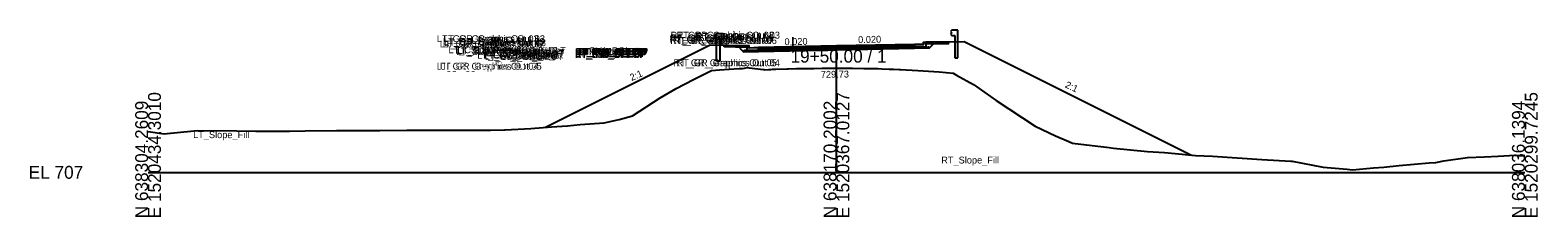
# Model space of a CAD drawing. Extents: x -26 to 3903, y -10 to 9531.
# Drawn here: x -25.7 to 302.8, y 9490.3 to 9531 of the extents above; entities that cross this region are included whole.
import ezdxf

# ---------------------------------------------------------------- set-up
doc = ezdxf.new("R2010")
doc.units = 0
for name, color, linetype in [('Default', 7, 'Continuous'), ('Exist Cross Section Cell', 7, 'Continuous'), ('Exist XS Center Line Elevation Label', 7, 'Continuous'), ('Exist XS Ground Line', 7, 'Continuous'), ('Old_Level_63', 7, 'Continuous'), ('Prop CMT Conc Surface', 7, 'Continuous'), ('Prop CMT Guardrail Graphics', 7, 'Continuous'), ('Prop CMT Pvmt Course 1', 7, 'Continuous'), ('Prop CMT Pvmt Course 1 CG', 7, 'Continuous'), ('Prop CMT Pvmt Course 2', 7, 'Continuous'), ('Prop CMT Pvmt Course 3', 7, 'Continuous'), ('Prop CMT Pvmt Surface', 7, 'Continuous'), ('Prop CMT Slope Grass', 7, 'Continuous'), ('Prop CMT Subgrade Earthwork', 7, 'Continuous'), ('Prop XS SE Text', 7, 'Continuous'), ('Prop XS Side Slope Text', 7, 'Continuous')]:
    doc.layers.add(name, color=color, linetype=linetype)

msp = doc.modelspace()

# ---------------------------------------------------------------- linework, layer by layer
at = {"layer": 'Exist Cross Section Cell'}
for p, q in [((150, 9500), (150, 9526.7)), ((0, 9500), (150, 9500)), ((150, 9500), (300, 9500))]:
    msp.add_line(p, q, dxfattribs=at)
at = {"layer": 'Exist XS Ground Line'}
msp.add_lwpolyline([(0, 9508.9), (3.5, 9508.42), (4.18, 9508.47), (6.32, 9508.7), (10.06, 9509.07), (10.85, 9509.15), (19.37, 9509.04), (23.49, 9508.96), (28.01, 9509), (30.83, 9508.99), (34.25, 9509.01), (41.07, 9509.12), (42.66, 9509.11), (50.49, 9509.12), (56.37, 9509.2), (60.6, 9509.17), (67.07, 9509.21), (74.63, 9509.16), (77.66, 9509.27), (77.82, 9509.28), (83.41, 9509.56), (87.92, 9509.89), (91.39, 9510.1), (94.14, 9510.42), (99.42, 9510.82), (102.65, 9511.51), (105.58, 9512.34), (111.57, 9516.22), (115.04, 9518.24), (118.87, 9520.21), (122.81, 9522.21), (124.52, 9522.3), (128.74, 9522.6), (129.53, 9522.64), (129.99, 9522.72), (130.63, 9522.85), (130.96, 9522.75), (134.11, 9522.4), (134.26, 9522.38), (134.29, 9522.37), (135.17, 9522.43), (135.53, 9522.42), (135.67, 9522.41), (136.09, 9522.46), (136.41, 9522.48), (136.42, 9522.48), (136.82, 9522.49), (139.26, 9522.55), (139.51, 9522.56), (141.29, 9522.61), (142.32, 9522.63), (144.81, 9522.66), (145.01, 9522.66), (145.11, 9522.66), (146.87, 9522.69), (147.9, 9522.69), (149.74, 9522.73), (150.12, 9522.73), (150.17, 9522.73), (150.45, 9522.73), (150.68, 9522.73), (151.01, 9522.72), (153.48, 9522.7), (155.94, 9522.65), (156.27, 9522.64), (158.02, 9522.61), (159.07, 9522.59), (159.89, 9522.56), (161.52, 9522.5), (161.84, 9522.49), (162.37, 9522.49), (162.38, 9522.49), (162.42, 9522.48), (163.66, 9522.44), (163.99, 9522.43), (167.77, 9522.19), (172.36, 9521.9), (175.4, 9521.63), (176.16, 9521.17), (179.85, 9519.14), (184.79, 9515.67), (193.27, 9510.04), (197.76, 9507.92), (200.67, 9506.74), (201.42, 9506.37), (209.42, 9505.41), (210.36, 9505.29), (217.81, 9504.56), (221.51, 9504.29), (225.31, 9503.95), (226.01, 9503.89), (228.24, 9503.7), (231.91, 9503.52), (242.73, 9502.82), (248.99, 9502.47), (249.32, 9502.42), (256.03, 9501.14), (261.32, 9500.7), (262.44, 9500.57), (267.04, 9500.98), (269.25, 9501.12), (272.64, 9501.49), (279.14, 9502.05), (280.58, 9502.16), (282.33, 9502.49), (287.5, 9503.24), (291.24, 9503.39), (294.17, 9503.53), (297.9, 9503.72), (298.9, 9503.68), (299.25, 9503.67), (300, 9503.65)], dxfattribs=at)
at = {"layer": 'Old_Level_63'}
for p, q in [((131, 9527.07), (131, 9527.57)), ((169, 9527.83), (167, 9527.87)), ((169, 9528.33), (169, 9527.83))]:
    msp.add_line(p, q, dxfattribs=at)
for points in [[(125.5, 9527.33), (125.5, 9527.67)], [(176.5, 9528.47), (169.5, 9528.33)], [(169.5, 9528.01), (174.5, 9528.1)], [(174.5, 9528.1), (174.5, 9528.43)], [(130.5, 9527.23), (125.5, 9527.33)]]:
    msp.add_lwpolyline(points, dxfattribs=at)
at = {"layer": 'Prop CMT Conc Surface'}
for points in [[(130.5, 9527.53), (125.5, 9527.63)], [(131, 9527.02), (131, 9527.52), (130.5, 9527.52)], [(167, 9527.82), (169, 9527.78)], [(169, 9527.78), (169, 9528.28), (169.5, 9528.28)], [(169.5, 9528.29), (174.5, 9528.39)], [(80.5, 9526.53), (75.5, 9526.63)], [(81, 9526.02), (81, 9526.52), (80.5, 9526.52)], [(83, 9526.14), (81, 9526.02)], [(133, 9527.14), (131, 9527.02)]]:
    msp.add_lwpolyline(points, dxfattribs=at)
at = {"layer": 'Prop CMT Guardrail Graphics'}
for points in [[(176.45, 9530.98), (175.12, 9530.98), (174.85, 9530.69)], [(176.45, 9524.98), (176.45, 9530.98)], [(123.9, 9524.22), (123.9, 9530.22)], [(123.9, 9530.22), (125.23, 9530.22), (125.5, 9529.93)], [(125.5, 9529.34), (125.23, 9529.05), (124.56, 9529.05)], [(124.56, 9529.05), (124.56, 9524.22)], [(125.5, 9529.93), (125.23, 9529.64)], [(125.23, 9529.64), (125.5, 9529.34)], [(174.85, 9530.69), (175.12, 9530.4)], [(175.12, 9530.4), (174.85, 9530.1)], [(174.85, 9530.1), (175.12, 9529.81), (175.79, 9529.81)], [(175.79, 9529.81), (175.79, 9524.98)], [(124.56, 9524.22), (123.9, 9524.22)], [(175.79, 9524.98), (176.45, 9524.98)]]:
    msp.add_lwpolyline(points, dxfattribs=at)
at = {"layer": 'Prop CMT Pvmt Course 1'}
for q in [(133, 9527.19), (167, 9527.87)]:
    msp.add_line((150, 9527.53), q, dxfattribs=at)
for points in [[(167, 9527.62), (150, 9527.28)], [(150, 9527.28), (150, 9527.53)], [(150, 9527.28), (150, 9527.53)], [(167, 9527.87), (167, 9527.62)], [(133, 9526.94), (150, 9527.28)], [(133, 9527.19), (133, 9526.94)]]:
    msp.add_lwpolyline(points, dxfattribs=at)
msp.add_lwpolyline([(150, 9527.28), (150, 9527.4), (150, 9527.4), (150, 9527.28)], close=True, dxfattribs=at)
msp.add_lwpolyline([(150, 9527.28), (150, 9527.4), (150, 9527.4), (150, 9527.28)], close=True, dxfattribs=at)
at = {"layer": 'Prop CMT Pvmt Course 1 CG'}
for points in [[(133, 9526.6), (130, 9526.54), (129.74, 9526.29)], [(129.74, 9526.29), (133, 9526.35)], [(133, 9526.35), (133, 9526.6)], [(167, 9527.28), (170, 9527.34), (170.25, 9527.1)], [(167, 9527.03), (167, 9527.28)], [(170.25, 9527.1), (167, 9527.03)]]:
    msp.add_lwpolyline(points, dxfattribs=at)
at = {"layer": 'Prop CMT Pvmt Course 2'}
for points in [[(150, 9527.28), (167, 9527.62)], [(167, 9527.62), (167, 9527.28)], [(150, 9527.28), (133, 9526.94)], [(133, 9526.6), (150, 9526.94)], [(133, 9526.94), (133, 9526.6)], [(150, 9526.94), (150, 9527.28)], [(167, 9527.28), (150, 9526.94)], [(150, 9526.94), (150, 9527.28)]]:
    msp.add_lwpolyline(points, dxfattribs=at)
at = {"layer": 'Prop CMT Pvmt Course 3'}
for points in [[(150, 9526.94), (133, 9526.6)], [(133, 9526.35), (150, 9526.69)], [(133, 9526.6), (133, 9526.35)], [(150, 9526.94), (167, 9527.28)], [(167, 9527.03), (150, 9526.69)], [(150, 9526.69), (150, 9526.94)], [(150, 9526.69), (150, 9526.94)], [(167, 9527.28), (167, 9527.03)]]:
    msp.add_lwpolyline(points, dxfattribs=at)
at = {"layer": 'Prop CMT Pvmt Surface'}
for p, q in [((150, 9527.53), (133, 9527.19)), ((167, 9527.87), (150, 9527.53))]:
    msp.add_line(p, q, dxfattribs=at)
for points in [[(150, 9527.53), (133, 9527.19)], [(150, 9527.53), (167, 9527.87)]]:
    msp.add_lwpolyline(points, dxfattribs=at)
at = {"layer": 'Prop CMT Slope Grass'}
msp.add_line((177.85, 9528.5), (227.36, 9503.74), dxfattribs=at)
for points in [[(122.5, 9527.73), (86.63, 9509.79)], [(130.5, 9527.57), (122.5, 9527.73)], [(133, 9527.19), (131, 9527.07), (131, 9527.57), (130.5, 9527.57)], [(130.5, 9527.57), (130.5, 9526.55), (133, 9526.6)], [(167, 9527.87), (169, 9527.83), (169, 9528.33), (169.5, 9528.33)], [(169.5, 9528.33), (169.5, 9527.33), (167, 9527.28)], [(167, 9527.28), (167, 9527.87)], [(169.5, 9528.33), (177.85, 9528.5)], [(133, 9526.6), (133, 9527.19)]]:
    msp.add_lwpolyline(points, dxfattribs=at)
at = {"layer": 'Prop CMT Subgrade Earthwork'}
for points in [[(133, 9526.35), (129.74, 9526.29), (128.43, 9527.61)], [(167, 9527.03), (170.25, 9527.1), (171.51, 9528.37)], [(150, 9526.69), (133, 9526.35)], [(150, 9526.69), (167, 9527.03)]]:
    msp.add_lwpolyline(points, dxfattribs=at)

# ---------------------------------------------------------------- texts
at = {"layer": 'Default'}
msp.add_text('-', height=0.0001, dxfattribs=at).set_placement((0, 9500))
at = {"layer": 'Exist Cross Section Cell'}
for s, p in [('L', (140, 9526.7)), ('19+50.00 / 1', (140, 9523.9)), ('EL 707', (-26, 9498.6))]:
    msp.add_text(s, height=2.8, dxfattribs=at).set_placement(p)
for s, p in [('N 638304.2609', (0, 9490)), ('E 1520434.3010', (2.8, 9490)), ('N 638170.2002', (150, 9490)), ('E 1520367.0127', (152.8, 9490)), ('N 638036.1394', (300, 9490)), ('E 1520299.7245', (302.8, 9490))]:
    msp.add_text(s, height=2.8, rotation=90, dxfattribs=at).set_placement(p)
at = {"layer": 'Exist XS Center Line Elevation Label'}
msp.add_text('729.73', height=1.5, rotation=0.8401, dxfattribs=at).set_placement((146.6, 9520.58))
at = {"layer": 'Prop CMT Conc Surface'}
for s, p in [('LT_GR_Graphics Out 03', (62.93, 9528.37)), ('LT_GR_Graphics Out 06', (63.58, 9527.21)), ('LT_GR_Graphics Out 07', (64.22, 9527.21)), ('LT_GR_Graphics Out 09', (64.25, 9527.79)), ('LT_GR_Graphics Out 02', (64.29, 9528.37)), ('LT_GR_Graphics Out 08', (64.51, 9527.5)), ('LT_CSLP_Pnt', (65.45, 9525.96)), ('LT_GR_Out', (70.37, 9528.08)), ('RT_GR_Graphics Out 08', (113.54, 9528.25)), ('RT_GR_Graphics Out 07', (113.8, 9527.96)), ('RT_GR_Graphics Out 09', (113.82, 9528.55)), ('RT_GR_Graphics Out 02', (113.86, 9529.13)), ('RT_GR_Graphics Out 06', (114.48, 9527.96)), ('RT_GR_Graphics Out 03', (115.17, 9529.13)), ('RT_GR_Out', (119.4, 9528.84)), ('LT_SDWK_Out_Top', (66.94, 9525.88)), ('LT_SDWK_Out_Bot', (67.12, 9525.55)), ('LT_Sub_Trench_Out_DLT', (67.4, 9525.81)), ('LT_CG1_Shelf_Out', (71.73, 9524.75)), ('LT_SDWK_In_Top', (72.8, 9525.78)), ('LT_CG_Top_BOC', (72.86, 9525.77)), ('LT_SDWK_In_Bot', (72.99, 9525.45)), ('LT_CG_Bot_BOC', (73.07, 9524.76)), ('LT_CG_Top_Face', (73.38, 9525.77)), ('LT_Sub_OEOP', (73.39, 9524.49)), ('LT_CG_Top_Gut', (73.78, 9525.27)), ('LT_PV2_OEOT', (76.62, 9525.14)), ('LT_PV3_OEOT', (76.62, 9524.81)), ('LT_Sub_OEOT', (76.65, 9524.56)), ('LT_PV1_OEOT', (76.8, 9525.39)), ('LT_CG_Bot_IE', (76.88, 9524.81)), ('RT_PV2_OEEOP', (93, 9525.48)), ('RT_PV3_OEEOP', (93, 9525.15)), ('RT_Sub_OEEOP', (93.04, 9524.9)), ('LT_PV2_OEEOP', (93.09, 9525.48)), ('LT_PV3_OEEOP', (93.09, 9525.15)), ('LT_Sub_OEEOP', (93.12, 9524.9)), ('RT_PV1_OEEOP', (93.18, 9525.61)), ('LT_PV1_OEEOP', (93.27, 9525.61)), ('RT_PV2_IEEOP', (93.57, 9525.48)), ('LT_PV2_IEEOP', (93.66, 9525.48)), ('RT_PV1_IEEOP', (93.75, 9525.61)), ('LT_PV1_IEEOP', (93.84, 9525.61)), ('PV2_PGL', (96.03, 9525.48)), ('PV1_PGL', (96.2, 9525.73)), ('RT_GR_Graphics Out 05', (114.49, 9523.13)), ('RT_GR_Graphics Out 04', (115.15, 9523.13)), ('LT_GR_Graphics Out 04', (62.91, 9522.37)), ('LT_GR_Graphics Out 05', (63.59, 9522.37)), ('LT_Slope_Fill', (9.81, 9507.45)), ('RT_Slope_Fill', (172.84, 9501.93))]:
    msp.add_text(s, height=1.5, dxfattribs=at).set_placement(p)
at = {"layer": 'Prop XS SE Text'}
for p in [(138.7, 9527.7), (154.74, 9528.16)]:
    msp.add_text('0.020', height=1.5, rotation=1.1458, dxfattribs=at).set_placement(p)
at = {"layer": 'Prop XS Side Slope Text'}
for rotation, p in [(23.9099, (105.37, 9519.88)), (334.8977, (199.68, 9518.56))]:
    msp.add_text('2:1', height=1.5, rotation=rotation, dxfattribs=at).set_placement(p)

doc.saveas('drawing.dxf')
